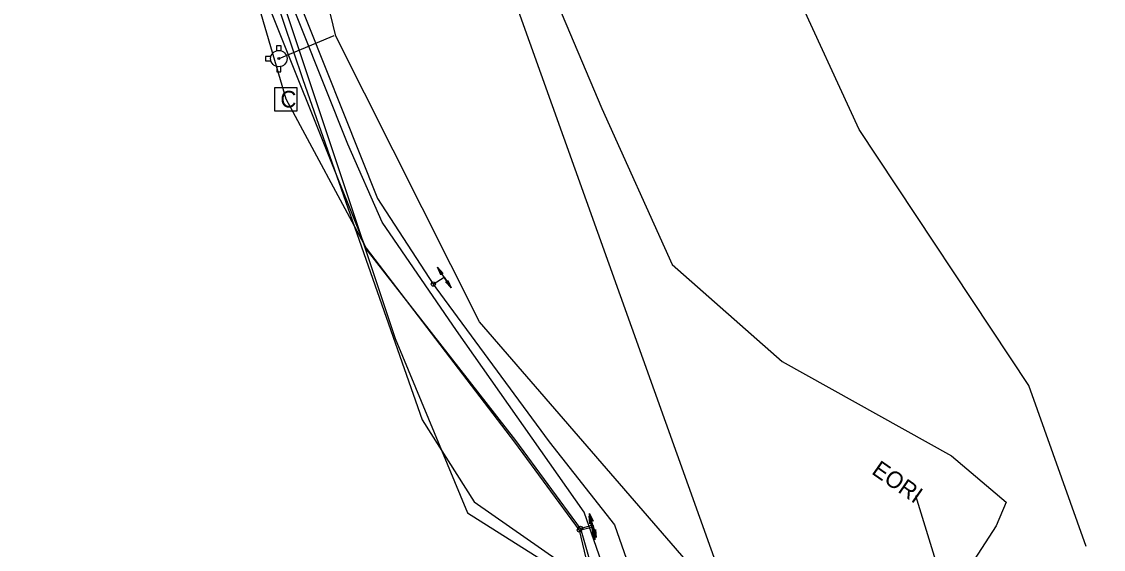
# Model space of a CAD drawing. Extents: x 2070721 to 2083340, y 729290 to 737883.
# Drawn here: x 2080186.1 to 2080447.3, y 734017.2 to 734144.7 of the extents above; entities that cross this region are included whole.
import ezdxf

# ---------------------------------------------------------------- set-up
doc = ezdxf.new("R2010")
doc.units = 0
for name, color, linetype in [('Exist Utilities Power UG Cable SUE LOS B', 7, 'Continuous'), ('Exist Utilities Power UG Cable SUE LOS C', 7, 'Continuous'), ('Exist Utilities Telephone Change of Service SUE CELL', 7, 'Continuous'), ('Exist Utilities Telephone UG Cable SUE LOS C', 7, 'Continuous'), ('Exist Utilities Telephone UG FO SUE LOS B', 7, 'Continuous'), ('Exist Utilities Telephone UG FO SUE LOS C', 7, 'Continuous'), ('Exist Utilities TV Change of Service SUE CELL', 7, 'Continuous'), ('Exist Utilities TV Hand Hole Text', 7, 'Continuous'), ('Exist Utilities TV Pedestal CELL', 7, 'Continuous'), ('Exist Utilities TV UG Cable SUE LOS C', 7, 'Continuous'), ('Exist Utilities TV UG FO Cable SUE LOS B', 7, 'Continuous'), ('Exist Utilities TV UG FO Cable SUE LOS C', 7, 'Continuous'), ('Exist Utilities Water Fire Hydrant CELL', 7, 'Continuous'), ('Exist Utilities Water UG Line SUE LOS B', 7, 'Continuous')]:
    doc.layers.add(name, color=color, linetype=linetype)

msp = doc.modelspace()

# ---------------------------------------------------------------- linework, layer by layer
at = {"layer": 'Exist Utilities Power UG Cable SUE LOS B'}
for points in [[(2080234.72, 734179.83), (2080241.98, 734171.12), (2080276.22, 734068.16), (2080293.76, 734026.09), (2080325.21, 734006.15), (2080360.35, 733978.15), (2080376.41, 733964.84), (2080394.21, 733967.31), (2080427.72, 733990.11), (2080441.72, 734003.26), (2080444.29, 734010.08)], [(2080443.09, 734017.91), (2080429.26, 734056.79), (2080388.33, 734118.62), (2080372.45, 734153.12), (2080414.03, 734167.36)]]:
    msp.add_lwpolyline(points, dxfattribs=at)
at = {"layer": 'Exist Utilities Power UG Cable SUE LOS C'}
for points in [[(2080186.05, 734475.29), (2080232.86, 734351.65), (2080379.47, 733942.04), (2080251.03, 733903.89)], [(2080225.45, 734168.4), (2080244.65, 734158.51), (2080253.95, 734130.69), (2080282.75, 734048.52), (2080295.34, 734028.75), (2080340.63, 733997.06), (2080355.06, 733989.84), (2080368.99, 733977.25), (2080380.73, 733968.31), (2080393.86, 733970.13), (2080428.86, 733995.36), (2080444.29, 734010.08)]]:
    msp.add_lwpolyline(points, dxfattribs=at)
at = {"layer": 'Exist Utilities Telephone Change of Service SUE CELL'}
for p, q in [((2080289.77, 734080.36), (2080286.51, 734085.35)), ((2080285.47, 734081.3), (2080288.06, 734082.98)), ((2080288.06, 734082.98), (2080289.77, 734080.36)), ((2080285.47, 734081.3), (2080285.47, 734081.3))]:
    msp.add_line(p, q, dxfattribs=at)
for points in [[(2080286.51, 734085.35), (2080287.88, 734083.89), (2080287.36, 734084.05), (2080287.31, 734083.57)], [(2080289.77, 734080.36), (2080288.41, 734081.82), (2080288.92, 734081.66), (2080288.97, 734082.14)]]:
    msp.add_lwpolyline(points, close=True, dxfattribs=at)
msp.add_circle((2080285.47, 734081.3), 0.517, dxfattribs=at)
at = {"layer": 'Exist Utilities Telephone UG Cable SUE LOS C'}
for points in [[(2080291.1, 734070.12), (2080273.08, 734096.26), (2080264.86, 734115.07), (2080247.85, 734157.71), (2080239.41, 734188.85), (2080232.9, 734211.26), (2080232.9, 734228.12), (2080231.97, 734244.9)], [(2080294.22, 734238.68), (2080294.22, 734221.46), (2080303.86, 734176.45), (2080326.14, 734123.68), (2080343.11, 734086.02), (2080369.71, 734062.6), (2080410.57, 734039.8), (2080423.78, 734028.65), (2080421.38, 734022.96), (2080402.46, 733993.71), (2080385.13, 733965.19), (2080355.27, 733912.59), (2080339.2, 733870.84), (2080335.53, 733861.67)], [(2080326.66, 734012.62), (2080321.93, 734026.22), (2080291.1, 734070.12)]]:
    msp.add_lwpolyline(points, dxfattribs=at)
at = {"layer": 'Exist Utilities Telephone UG FO SUE LOS B'}
msp.add_lwpolyline([(2080234.38, 734213.72), (2080251.15, 734154.39), (2080272, 734101.95), (2080285.47, 734081.3)], dxfattribs=at)
at = {"layer": 'Exist Utilities Telephone UG FO SUE LOS C'}
for points in [[(2080285.47, 734081.3), (2080286.04, 734080.39), (2080313.44, 734043.19), (2080329.21, 734023.2), (2080334.41, 734008.43), (2080328.94, 733989.17)], [(2080336.57, 733860.97), (2080338.22, 733863.58), (2080337.51, 733869.77), (2080348.05, 733900.55), (2080371.36, 733947.72), (2080396.33, 733986.42), (2080408.45, 734009.24), (2080401.96, 734030.18)]]:
    msp.add_lwpolyline(points, dxfattribs=at)
at = {"layer": 'Exist Utilities TV Change of Service SUE CELL'}
for p, q in [((2080324.45, 734019.56), (2080323.09, 734025.37)), ((2080324.83, 734020.14), (2080323.2, 734025.87)), ((2080320.73, 734021.92), (2080323.73, 734022.62)), ((2080321.01, 734022.31), (2080323.97, 734023.16)), ((2080323.73, 734022.62), (2080324.45, 734019.56)), ((2080323.97, 734023.16), (2080324.83, 734020.14)), ((2080320.73, 734021.92), (2080320.73, 734021.92)), ((2080321.01, 734022.31), (2080321.01, 734022.31))]:
    msp.add_line(p, q, dxfattribs=at)
for points in [[(2080323.09, 734025.37), (2080323.87, 734023.53), (2080323.44, 734023.86), (2080323.23, 734023.42)], [(2080323.2, 734025.87), (2080324.07, 734024.07), (2080323.62, 734024.38), (2080323.43, 734023.93)], [(2080324.45, 734019.56), (2080323.67, 734021.4), (2080324.1, 734021.07), (2080324.31, 734021.52)], [(2080324.83, 734020.14), (2080323.96, 734021.94), (2080324.41, 734021.63), (2080324.6, 734022.08)]]:
    msp.add_lwpolyline(points, close=True, dxfattribs=at)
for centre in [(2080320.73, 734021.92), (2080321.01, 734022.31)]:
    msp.add_circle(centre, 0.517, dxfattribs=at)
at = {"layer": 'Exist Utilities TV Pedestal CELL'}
msp.add_line((2080249.85, 734125.95), (2080249.85, 734125.95), dxfattribs=at)
msp.add_lwpolyline([(2080247.08, 734123.17), (2080252.63, 734123.17), (2080252.63, 734128.72), (2080247.08, 734128.72), (2080247.08, 734123.17)], dxfattribs=at)
at = {"layer": 'Exist Utilities TV UG Cable SUE LOS C'}
for points in [[(2080228.33, 734237.2), (2080227.59, 734213.41), (2080238.77, 734164.01), (2080249.82, 734126.01), (2080269.26, 734089.95), (2080305.09, 734043.13), (2080320.73, 734021.92)], [(2080320.73, 734021.92), (2080323.11, 734011.73), (2080323.11, 733999.23)]]:
    msp.add_lwpolyline(points, dxfattribs=at)
at = {"layer": 'Exist Utilities TV UG FO Cable SUE LOS B'}
msp.add_lwpolyline([(2080321.01, 734022.31), (2080305.36, 734043.56), (2080269.25, 734089.82), (2080239.52, 734164.02)], dxfattribs=at)
at = {"layer": 'Exist Utilities TV UG FO Cable SUE LOS C'}
msp.add_lwpolyline([(2080321.01, 734022.31), (2080323.92, 734012.13), (2080323.35, 733999.94)], dxfattribs=at)
at = {"layer": 'Exist Utilities Water Fire Hydrant CELL'}
msp.add_line((2080248.17, 734135.75), (2080248.17, 734135.75), dxfattribs=at)
for points in [[(2080247.66, 734137.66), (2080247.66, 734138.95), (2080248.68, 734138.95), (2080248.68, 734137.64)], [(2080246.26, 734136.26), (2080244.97, 734136.26), (2080244.97, 734135.24), (2080246.26, 734135.24)], [(2080247.66, 734133.84), (2080247.66, 734132.55), (2080248.68, 734132.55), (2080248.68, 734133.86)]]:
    msp.add_lwpolyline(points, dxfattribs=at)
for radius in [1.98, 0.243]:
    msp.add_circle((2080248.17, 734135.75), radius, dxfattribs=at)
at = {"layer": 'Exist Utilities Water UG Line SUE LOS B'}
msp.add_line((2080248.24, 734135.8), (2080261.53, 734141.3), dxfattribs=at)
msp.add_lwpolyline([(2080357.06, 734003.27), (2080353.32, 734006.79), (2080296.63, 734072.2), (2080261.95, 734141.13), (2080251.22, 734185.42), (2080250, 734189.2), (2080244.12, 734248.6), (2080244.13, 734251.5), (2080244.63, 734259.68), (2080245.13, 734264.1), (2080254.44, 734320.44), (2080276.53, 734380.91), (2080391.41, 734503.18), (2080497.9, 734548.7), (2080500.72, 734549.83), (2080585.45, 734578.7), (2080702.53, 734619.89), (2080710.17, 734622.62), (2080743.51, 734634.52), (2080754.26, 734638.28), (2080902.52, 734692.58), (2081024.44, 734735.33)], dxfattribs=at)

# ---------------------------------------------------------------- texts
at = {"layer": 'Exist Utilities TV Hand Hole Text'}
msp.add_text('EORI', height=4, rotation=325.1618, dxfattribs=at).set_placement((2080391.09, 734035.64))
at = {"layer": 'Exist Utilities TV Pedestal CELL'}
msp.add_text('C', height=4, dxfattribs=at).set_placement((2080248.54, 734123.95))

doc.saveas('drawing.dxf')
